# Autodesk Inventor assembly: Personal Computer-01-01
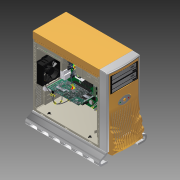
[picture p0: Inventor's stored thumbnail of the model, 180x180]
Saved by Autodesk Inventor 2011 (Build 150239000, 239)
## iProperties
Company: Autodesk Inc.
Created: 2008-02
Part Number: Personal Computer-01-01
Document SubType Name: Assembly
Designer: hendert
Mass: 5059.49 g
Surface Area: 31504.8 cm^2
Volume: 5059.49 cm^3
Density: 1 g/cm^3
Title: Personal Computer
Author: hendert
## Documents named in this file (17)
- C:\Users\Public\Documents\Autodesk\Inventor 2011\Samples\Models\Assemblies\Personal Computer\Personal Computer\Inventor PC Case.iam
- C:\Users\Public\Documents\Autodesk\Inventor 2011\Samples\Models\Assemblies\Personal Computer\PC Chassis\PC Chassis.iam
- C:\Users\Public\Documents\Autodesk\Inventor 2011\Samples\Models\Assemblies\Personal Computer\Motherboard\Motherboard.iam
- C:\Users\Public\Documents\Autodesk\Inventor 2011\Samples\Models\Assemblies\Personal Computer\Graphics Card\Graphics Card.iam
- C:\Users\Public\Documents\Autodesk\Inventor 2011\Samples\Models\Assemblies\Personal Computer\Power Supply\Power Supply.iam
- C:\Users\Public\Documents\Autodesk\Inventor 2011\Samples\Models\Assemblies\Personal Computer\Drives\CDROM.ipt
- C:\Users\Public\Documents\Autodesk\Inventor 2011\Samples\Models\Assemblies\Personal Computer\Drives\Hard Drive.ipt
- C:\Users\Public\Documents\Autodesk\Inventor 2011\Samples\Models\Assemblies\Personal Computer\Aip\CD Ribbon Cable.iam
- C:\Users\Public\Documents\Autodesk\Inventor 2011\Samples\Models\Assemblies\Personal Computer\PC Cover\Inventor PC Cover\Case Top.ipt
- C:\Users\Public\Documents\Autodesk\Inventor 2011\Samples\Models\Assemblies\Personal Computer\PC Cover\Inventor PC Cover\Stylistic Front Face.ipt
- C:\Users\Public\Documents\Autodesk\Inventor 2011\Samples\Models\Assemblies\Personal Computer\PC Cover\Inventor PC Cover\LED Button.ipt
- C:\Users\Public\Documents\Autodesk\Inventor 2011\Samples\Models\Assemblies\Personal Computer\Aip\Power Supply Harness.iam
- C:\Users\Public\Documents\Autodesk\Inventor 2011\Samples\Models\Assemblies\Personal Computer\Aip\Cooling Fan Harness.iam
- C:\Users\Public\Documents\Autodesk\Inventor 2011\Samples\Models\Assemblies\Personal Computer\Aip\Processor Fan Harness.iam
- C:\Users\Public\Documents\Autodesk\Inventor 2011\Samples\Models\Assemblies\Personal Computer\Aip\Front Panel Harness.iam
- C:\Users\Public\Documents\Autodesk\Inventor 2011\Samples\Models\Assemblies\Personal Computer\Aip\HD Ribbon Cable.iam
- C:\Users\Public\Documents\Autodesk\Inventor 2011\Samples\Models\Assemblies\Personal Computer\Personal Computer.iam
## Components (17 placed, 15 different names)
1. PC Chassis:1 [sub-assembly] — Mate:1, Mate:3, Mate:7, Mate:8, Mate:9, Mate:10, Mate:11, Angle:1, Mate:12, Mate:13, Angle:2, Mate:14, Mate:15, Angle:3, Mate:16, Mate:17, Angle:4, Mate:79, Mate:80, Mate:81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
2. Case Top:1 — Mate:79, Mate:80, Mate:81, Mate:82, Flush:5
3. Stylistic Front Face:1 — Mate:82, Flush:5, Mate:83, Mate:85, Mate:86
4. LED Button:1 — Mate:84, Mate:85, Mate:86
5. Power Supply:1 [sub-assembly] — Mate:7, Mate:8, Mate:9, Mate:87, Mate:88, Mate:89, Mate:90, Mate:91, Mate:92, Mate:93, Mate:94, Mate:95, Mate:96, Mate:97, Mate:98, Mate:99, Mate:100, Mate:101, Mate:102, Mate:103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
6. Motherboard:1 [sub-assembly] — Mate:5, Mate:6, Mate:32, Mate:33, Mate:34, Mate:107, Flush:10, Flush:11, Mate:108, Flush:12, Flush:13, Mate:121, Mate:122, Mate:123, Mate:124, Mate:125, Mate:126, Mate:127, Mate:128, Mate:129
7. Graphics Card:1 [sub-assembly] — Mate:1, Mate:3, Mate:5, Mate:6
8. CDROM:1 — Mate:10, Mate:11, Angle:1, Mate:44, Mate:45, Mate:46, Mate:109, Mate:110, Mate:111
9. CDROM:2 — Mate:12, Mate:13, Angle:2, Mate:38, Mate:39, Mate:40, Mate:112, Mate:113, Mate:114
10. Hard Drive:1 — Mate:16, Mate:17, Angle:4, Mate:115, Mate:116, Mate:117, Mate:133, Mate:134, Mate:135
11. Hard Drive:2 — Mate:14, Mate:15, Angle:3, Mate:118, Mate:119, Mate:120, Mate:130, Mate:131, Mate:132
12. CD Ribbon Cable [sub-assembly] — Mate:32, Mate:33, Mate:34, Mate:38, Mate:39, Mate:40, Mate:44, Mate:45, Mate:46
13. Power Supply Harness [sub-assembly] — Mate:87, Mate:88, Mate:89, Mate:90, Mate:91, Mate:92, Mate:93, Mate:94, Mate:95, Mate:96, Mate:97, Mate:98, Mate:99, Mate:100, Mate:101, Mate:102, Mate:103, Mate:104, Mate:105, Mate:106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
14. Cooling Fan Harness [sub-assembly]
15. Processor Fan Harness [sub-assembly] — Mate:121, Mate:122, Mate:123
16. Front Panel Harness [sub-assembly] — Mate:124, Mate:125, Mate:126
17. HD Ribbon Cable [sub-assembly] — Mate:127, Mate:128, Mate:129, Mate:130, Mate:131, Mate:132, Mate:133, Mate:134, Mate:135
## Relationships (90: Mate 81, Flush 5, Angle 4)
- Mate:1: PC Chassis:1 ↔ Graphics Card:1
- Mate:3: PC Chassis:1 ↔ Graphics Card:1
- Mate:5: Motherboard:1 ↔ Graphics Card:1
- Mate:6: Motherboard:1 ↔ Graphics Card:1
- Mate:7: PC Chassis:1 ↔ Power Supply:1
- Mate:8: PC Chassis:1 ↔ Power Supply:1
- Mate:9: PC Chassis:1 ↔ Power Supply:1
- Mate:10: PC Chassis:1 ↔ CDROM:1
- Mate:11: PC Chassis:1 ↔ CDROM:1
- Angle:1: PC Chassis:1 ↔ CDROM:1
- Mate:12: PC Chassis:1 ↔ CDROM:2
- Mate:13: PC Chassis:1 ↔ CDROM:2
- Angle:2: PC Chassis:1 ↔ CDROM:2
- Mate:14: PC Chassis:1 ↔ Hard Drive:2
- Mate:15: PC Chassis:1 ↔ Hard Drive:2
- Angle:3: PC Chassis:1 ↔ Hard Drive:2
- Mate:16: PC Chassis:1 ↔ Hard Drive:1
- Mate:17: PC Chassis:1 ↔ Hard Drive:1
- Angle:4: PC Chassis:1 ↔ Hard Drive:1
- Mate:32: Motherboard:1 ↔ CD Ribbon Cable
- Mate:33: Motherboard:1 ↔ CD Ribbon Cable
- Mate:34: Motherboard:1 ↔ CD Ribbon Cable
- Mate:38: CDROM:2 ↔ CD Ribbon Cable
- Mate:39: CDROM:2 ↔ CD Ribbon Cable
- Mate:40: CDROM:2 ↔ CD Ribbon Cable
- Mate:44: CDROM:1 ↔ CD Ribbon Cable
- Mate:45: CDROM:1 ↔ CD Ribbon Cable
- Mate:46: CDROM:1 ↔ CD Ribbon Cable
- Mate:79: PC Chassis:1 ↔ Case Top:1
- Mate:80: PC Chassis:1 ↔ Case Top:1
- Mate:81: PC Chassis:1 ↔ Case Top:1
- Mate:82: Case Top:1 ↔ Stylistic Front Face:1
- Flush:5: Case Top:1 ↔ Stylistic Front Face:1
- Mate:83: PC Chassis:1 ↔ Stylistic Front Face:1
- Mate:84: PC Chassis:1 ↔ LED Button:1
- Mate:85: Stylistic Front Face:1 ↔ LED Button:1
- Mate:86: Stylistic Front Face:1 ↔ LED Button:1
- Mate:87: Power Supply:1 ↔ Power Supply Harness
- Mate:88: Power Supply:1 ↔ Power Supply Harness
- Mate:89: Power Supply:1 ↔ Power Supply Harness
- Mate:90: Power Supply:1 ↔ Power Supply Harness
- Mate:91: Power Supply:1 ↔ Power Supply Harness
- Mate:92: Power Supply:1 ↔ Power Supply Harness
- Mate:93: Power Supply:1 ↔ Power Supply Harness
- Mate:94: Power Supply:1 ↔ Power Supply Harness
- Mate:95: Power Supply:1 ↔ Power Supply Harness
- Mate:96: Power Supply:1 ↔ Power Supply Harness
- Mate:97: Power Supply:1 ↔ Power Supply Harness
- Mate:98: Power Supply:1 ↔ Power Supply Harness
- Mate:99: Power Supply:1 ↔ Power Supply Harness
- Mate:100: Power Supply:1 ↔ Power Supply Harness
- Mate:101: Power Supply:1 ↔ Power Supply Harness
- Mate:102: Power Supply:1 ↔ Power Supply Harness
- Mate:103: Power Supply:1 ↔ Power Supply Harness
- Mate:104: Power Supply:1 ↔ Power Supply Harness
- Mate:105: Power Supply:1 ↔ Power Supply Harness
- Mate:106: Power Supply:1 ↔ Power Supply Harness
- Mate:107: Motherboard:1 ↔ Power Supply Harness
- Flush:10: Motherboard:1 ↔ Power Supply Harness
- Flush:11: Motherboard:1 ↔ Power Supply Harness
- Mate:108: Motherboard:1 ↔ Power Supply Harness
- Flush:12: Motherboard:1 ↔ Power Supply Harness
- Flush:13: Motherboard:1 ↔ Power Supply Harness
- Mate:109: CDROM:1 ↔ Power Supply Harness
- Mate:110: CDROM:1 ↔ Power Supply Harness
- Mate:111: CDROM:1 ↔ Power Supply Harness
- Mate:112: CDROM:2 ↔ Power Supply Harness
- Mate:113: CDROM:2 ↔ Power Supply Harness
- Mate:114: CDROM:2 ↔ Power Supply Harness
- Mate:115: Hard Drive:1 ↔ Power Supply Harness
- Mate:116: Hard Drive:1 ↔ Power Supply Harness
- Mate:117: Hard Drive:1 ↔ Power Supply Harness
- Mate:118: Hard Drive:2 ↔ Power Supply Harness
- Mate:119: Hard Drive:2 ↔ Power Supply Harness
- Mate:120: Hard Drive:2 ↔ Power Supply Harness
- Mate:121: Motherboard:1 ↔ Processor Fan Harness
- Mate:122: Motherboard:1 ↔ Processor Fan Harness
- Mate:123: Motherboard:1 ↔ Processor Fan Harness
- Mate:124: Motherboard:1 ↔ Front Panel Harness
- Mate:125: Motherboard:1 ↔ Front Panel Harness
- Mate:126: Motherboard:1 ↔ Front Panel Harness
- Mate:127: Motherboard:1 ↔ HD Ribbon Cable
- Mate:128: Motherboard:1 ↔ HD Ribbon Cable
- Mate:129: Motherboard:1 ↔ HD Ribbon Cable
- Mate:130: Hard Drive:2 ↔ HD Ribbon Cable
- Mate:131: Hard Drive:2 ↔ HD Ribbon Cable
- Mate:132: Hard Drive:2 ↔ HD Ribbon Cable
- Mate:133: Hard Drive:1 ↔ HD Ribbon Cable
- Mate:134: Hard Drive:1 ↔ HD Ribbon Cable
- Mate:135: Hard Drive:1 ↔ HD Ribbon Cable
